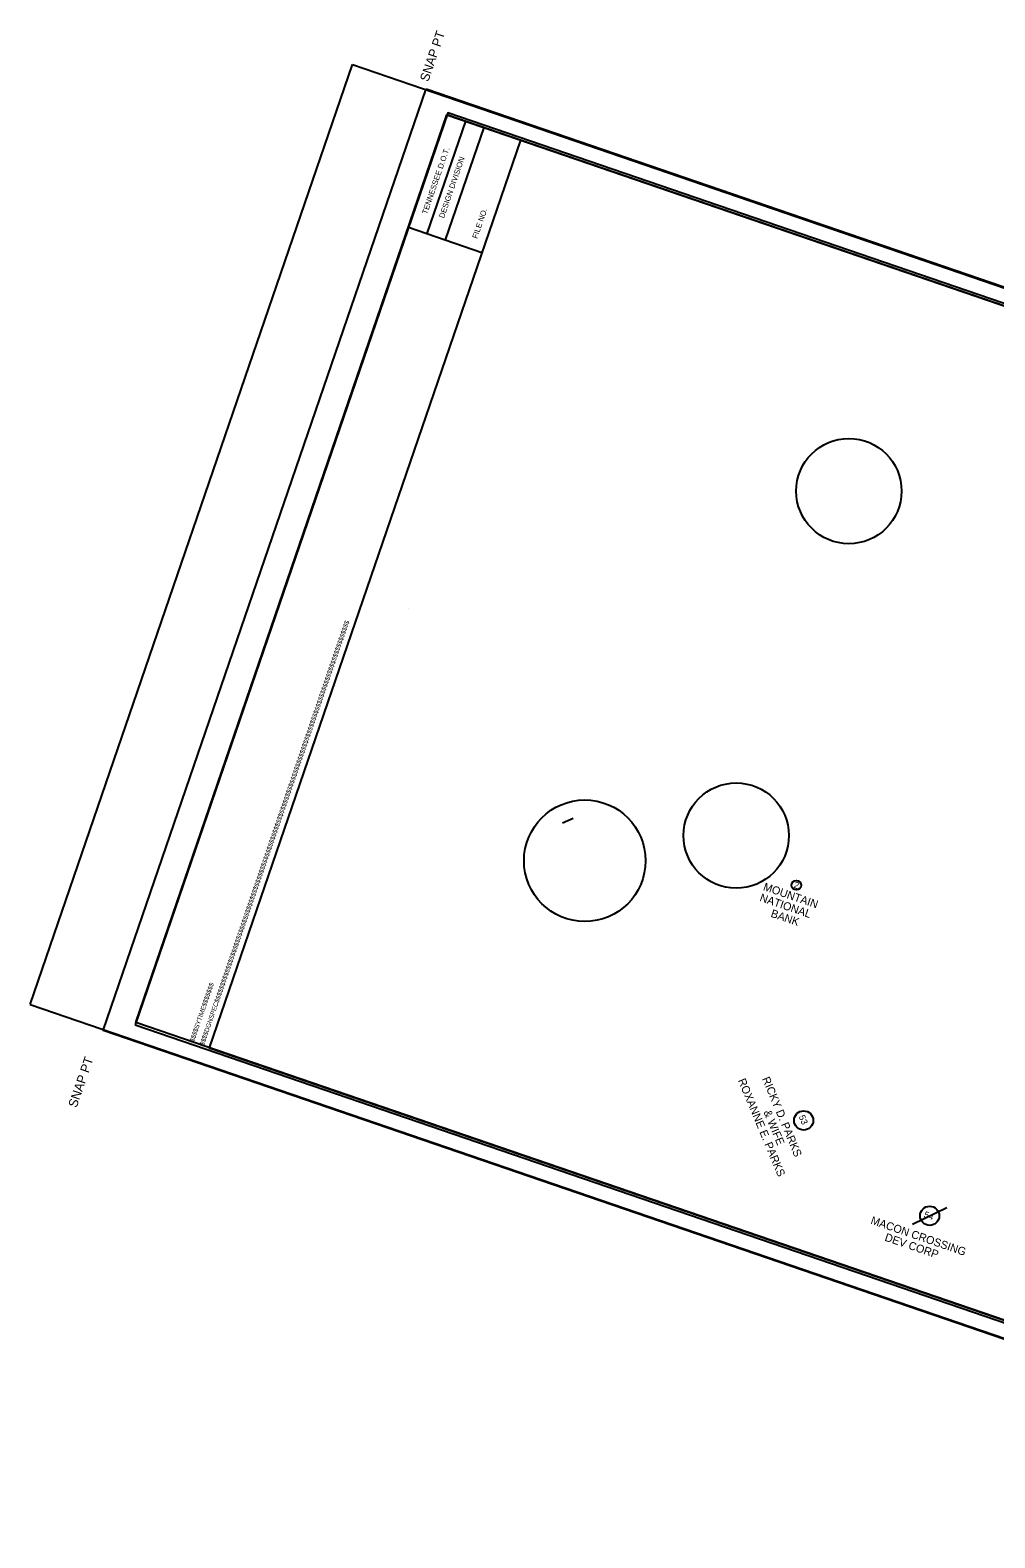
# Model space of a CAD drawing. Extents: x 2626331 to 2628652, y 569305 to 571035.
# Drawn here: x 2626331 to 2627386, y 569386 to 571035 of the extents above; entities that cross this region are included whole.
import ezdxf

# ---------------------------------------------------------------- set-up
doc = ezdxf.new("R2010")
doc.units = 0
for name, color, linetype in [('DESIGN - SCRATCH - User 1', 7, 'Continuous'), ('DESIGN - SHEET - Corner Text', 7, 'Continuous'), ('DESIGN - SHEET - Light Grid', 7, 'Continuous'), ('DESIGN - SHEET - Linework', 7, 'Continuous'), ('DESIGN - SHEET - Plot Shape', 7, 'Continuous'), ('SURVEY - CONTROL with Text', 7, 'Continuous'), ('SURVEY - GROUND - Top of Rock Layer', 7, 'Continuous'), ('SURVEY - PROPERTY - Owners', 7, 'Continuous'), ('SURVEY - PROPERTY - Tract Numbers', 7, 'Continuous')]:
    doc.layers.add(name, color=color, linetype=linetype)

msp = doc.modelspace()

# ---------------------------------------------------------------- linework, layer by layer
at = {"layer": 'DESIGN - SCRATCH - User 1'}
msp.add_line((2626744.1, 570402.3), (2626744.1, 570402.3), dxfattribs=at)
at = {"layer": 'DESIGN - SHEET - Light Grid'}
msp.add_lwpolyline([(2626445.3, 569947.1), (2628020.3, 569407.2), (2628362.4, 570405.2), (2626787.4, 570945.1)], close=True, dxfattribs=at)
at = {"layer": 'DESIGN - SHEET - Linework'}
for p, q in [((2626330.5, 569969.3), (2626683.1, 570997.9)), ((2626683.1, 570997.9), (2628385.9, 570414.3)), ((2626806.7, 570935.8), (2626764.5, 570812.9)), ((2626826.8, 570928.9), (2626784.7, 570806)), ((2626330.5, 569969.3), (2628033.2, 569385.6))]:
    msp.add_line(p, q, dxfattribs=at)
for points in [[(2626867, 570915.1), (2626786.5, 570942.7), (2626744.4, 570819.8), (2626824.9, 570792.3)], [(2626867, 570915.1), (2626526.5, 569921.9), (2628015.7, 569411.4), (2628356.1, 570404.7), (2626867, 570915.1)]]:
    msp.add_lwpolyline(points, dxfattribs=at)
at = {"layer": 'DESIGN - SHEET - Plot Shape'}
for points in [[(2626763.7, 570971.4), (2628371.8, 570420.1), (2628018.6, 569389.6), (2626410.4, 569940.8)], [(2626786.5, 570942.7), (2628356.1, 570404.7), (2628015.7, 569411.4), (2626446.1, 569949.5)]]:
    msp.add_lwpolyline(points, close=True, dxfattribs=at)
at = {"layer": 'SURVEY - CONTROL with Text'}
for centre, radius in [((2627226.4, 570531.1), 57.6), ((2627103.1, 570154.1), 57.6), ((2626937.4, 570126.6), 66.5)]:
    msp.add_circle(centre, radius, dxfattribs=at)
at = {"layer": 'SURVEY - GROUND - Top of Rock Layer'}
msp.add_line((2626912.9, 570168.1), (2626924.8, 570173), dxfattribs=at)
at = {"layer": 'SURVEY - PROPERTY - Tract Numbers'}
msp.add_line((2627295.9, 569728.7), (2627333.6, 569747.2), dxfattribs=at)
for centre, radius in [((2627168.9, 570099.8), 5.25), ((2627176.9, 569842.4), 10.5), ((2627314.8, 569738), 10.5)]:
    msp.add_circle(centre, radius, dxfattribs=at)

# ---------------------------------------------------------------- texts
at = {"layer": 'DESIGN - SHEET - Corner Text'}
for s, height, p in [('  SNAP PT', 10, (2626763.7, 570971.4)), ('TENNESSEE D.O.T.', 6, (2626764.8, 570833.5)), ('DESIGN DIVISION', 6, (2626783.3, 570829.2)), ('FILE NO.', 6, (2626819.7, 570806.8)), ('$$$$DGNSPEC$$$$$$$$$$$$$$$$$$$$$$$$$$$$$$$$$$$$$$$$$$$$$$$$$$$$$$$$$$$$$$$$$$$$$$$$$$$$$$$$$$$$$$$$$$$$$$$$$$$$$$$$$$$$$$$$$$$', 5.0001, (2626520.6, 569923.9)), ('$$$$SYTIME$$$$$$$', 5, (2626509.6, 569927.7)), ('SNAP PT  ', 10, (2626381.3, 569855.7))]:
    msp.add_text(s, height=height, rotation=71.0785, dxfattribs=at).set_placement(p)
at = {"layer": 'SURVEY - PROPERTY - Owners'}
for s, rotation, p in [('MOUNTAIN', 341.0785, (2627131.9, 570094.6)), ('NATIONAL', 341.0785, (2627128.1, 570082.7)), ('BANK', 341.0785, (2627140.2, 570065.4)), ('ROXANNE E. PARKS', 292.6154, (2627104.8, 569886.2)), ('RICKY D. PARKS', 292.6154, (2627131.2, 569888)), ('& WIFE', 292.6154, (2627132.8, 569851.6)), ('MACON CROSSING', 341.0785, (2627249.5, 569729.5)), ('DEV CORP ', 341.0785, (2627264.9, 569711))]:
    msp.add_text(s, height=8.75, rotation=rotation, dxfattribs=at).set_placement(p)
at = {"layer": 'SURVEY - PROPERTY - Tract Numbers'}
for s, rotation, p in [('2', 341.0785, (2627165.4, 570097.3)), ('53', 292.6154, (2627171.4, 569846.6)), ('54', 341.0785, (2627307.9, 569736.6))]:
    msp.add_text(s, height=7, rotation=rotation, dxfattribs=at).set_placement(p)

doc.saveas('drawing.dxf')
